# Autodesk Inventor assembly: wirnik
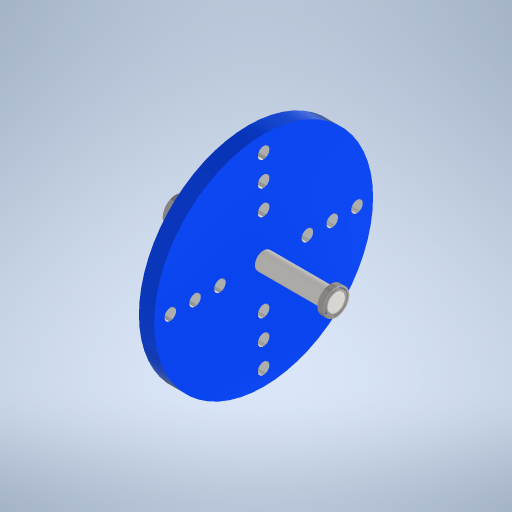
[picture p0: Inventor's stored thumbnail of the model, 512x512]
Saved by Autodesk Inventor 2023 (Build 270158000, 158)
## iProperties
Created: 2023-02
Part Number: wirnik
Document SubType Name: Assembly
Designer: Admin
Author: Admin
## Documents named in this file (4)
- C:\Users\Admin\Desktop\DYNAMIKA MASZYN zmiany\nowe laboratorium mechatronika 2021\nowe lab04 - drgania swobodne\wał_i_krazek\wirnik.iam
- C:\Users\Admin\Desktop\DYNAMIKA MASZYN zmiany\nowe laboratorium mechatronika 2021\nowe lab04 - drgania swobodne\wał_i_krazek\shaft.ipt
- C:\Users\Admin\Desktop\DYNAMIKA MASZYN zmiany\nowe laboratorium mechatronika 2021\nowe lab04 - drgania swobodne\wał_i_krazek\disk.ipt
- C:\Users\Admin\Documents\Inventor\Content Center Files\R2023\pl-PL\UNI ISO 15\ISO 15 - 7 17 12 x 18 x 4.ipt
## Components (4 placed, 3 different names)
1. shaft:1 — Zestawiające:1, Równoległe:1, Zestawiające:2, Równoległe:2, Zestawiające:3, Równoległe:3
2. disk:1 — Zestawiające:1, Równoległe:1
3. UNI ISO 15 7 17 12 x 18 x 4:1 — Zestawiające:2, Równoległe:2
4. UNI ISO 15 7 17 12 x 18 x 4:2 — Zestawiające:3, Równoległe:3
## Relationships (6: Mate 3, Flush 3)
- Zestawiające:1 [Mate]: shaft:1 ↔ disk:1
- Równoległe:1 [Flush]: shaft:1 ↔ disk:1
- Zestawiające:2 [Mate]: shaft:1 ↔ UNI ISO 15 7 17 12 x 18 x 4:1
- Równoległe:2 [Flush]: shaft:1 ↔ UNI ISO 15 7 17 12 x 18 x 4:1
- Zestawiające:3 [Mate]: shaft:1 ↔ UNI ISO 15 7 17 12 x 18 x 4:2
- Równoległe:3 [Flush]: shaft:1 ↔ UNI ISO 15 7 17 12 x 18 x 4:2
